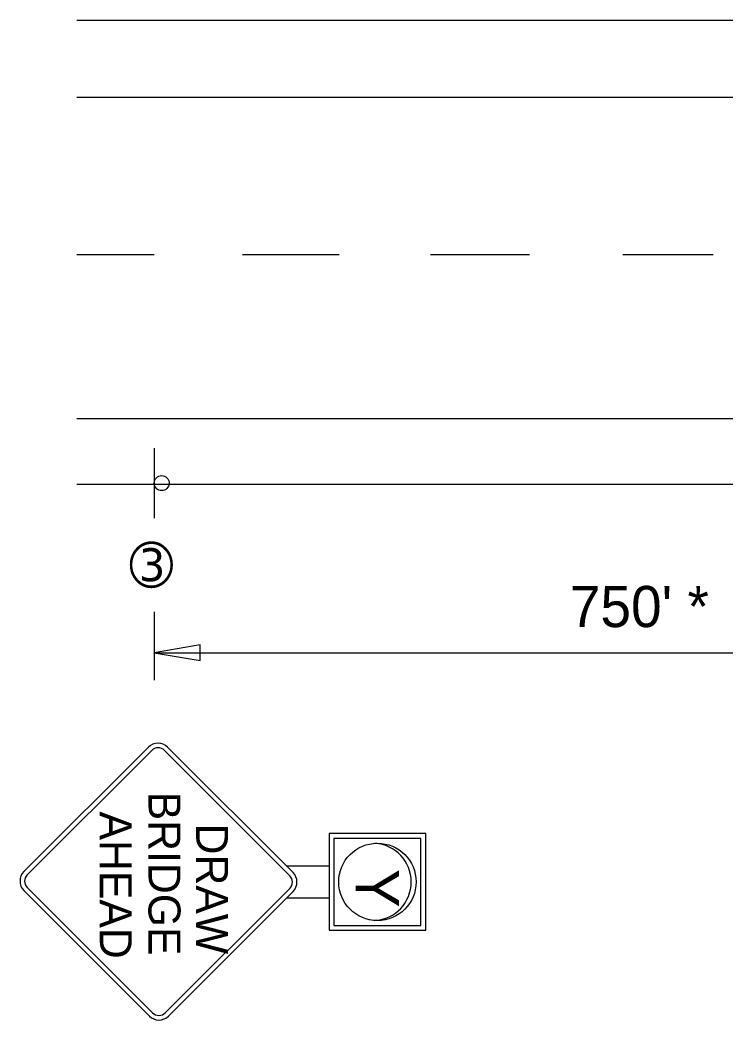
# Model space of a CAD drawing. Extents: x 15 to 764, y 7 to 487.
# Drawn here: x 17.2 to 77.2, y 347.6 to 432.6 of the extents above; entities that cross this region are included whole.
import ezdxf

# ---------------------------------------------------------------- set-up
doc = ezdxf.new("R2010")
doc.units = 0
for name, color, linetype in [('Default', 7, 'Continuous'), ('Dimension', 7, 'Continuous'), ('TextStructures', 7, 'Continuous')]:
    doc.layers.add(name, color=color, linetype=linetype)

msp = doc.modelspace()

# ---------------------------------------------------------------- linework, layer by layer
at = {"layer": 'Default'}
for p, q in [((22.063, 432.626), (366.864, 432.626)), ((22.063, 426.064), (366.864, 426.064)), ((22.063, 412.687), (28.635, 412.687)), ((36.151, 412.687), (44.369, 412.687)), ((52.111, 412.687), (60.533, 412.687)), ((68.478, 412.687), (76.153, 412.687)), ((22.063, 398.745), (366.864, 398.745)), ((28.637, 396.213), (28.637, 390.268)), ((22.063, 393.153), (366.864, 393.153)), ((28.646, 382.31), (28.646, 376.494)), ((28.646, 378.825), (114.544, 378.825)), ((17.568, 360.214), (28.153, 370.793)), ((29.778, 370.793), (40.438, 360.13)), ((17.843, 359.941), (28.428, 370.519)), ((29.505, 370.519), (40.163, 359.855)), ((43.501, 363.44), (43.501, 355.22)), ((51.721, 363.44), (43.501, 363.44)), ((51.721, 355.22), (51.721, 363.44)), ((43.912, 363.029), (43.912, 355.631)), ((51.31, 363.029), (43.912, 363.029)), ((51.31, 355.631), (51.31, 363.029)), ((39.861, 360.707), (43.49, 360.707)), ((17.568, 358.587), (28.227, 347.925)), ((17.843, 358.862), (28.501, 348.198)), ((29.578, 348.198), (40.162, 358.778)), ((29.852, 347.925), (40.437, 358.503)), ((39.923, 357.99), (43.49, 357.99)), ((43.912, 355.631), (51.31, 355.631)), ((43.501, 355.22), (51.721, 355.22))]:
    msp.add_line(p, q, dxfattribs=at)
for centre, radius in [((29.274, 393.241), 0.637), ((47.611, 359.33), 3.288)]:
    msp.add_circle(centre, radius, dxfattribs=at)
for centre, radius, start, end in [((28.966, 369.98), 1.15, 44.98473, 134.98571), ((28.966, 369.98), 0.762, 44.98473, 134.98571), ((47.2, 359.33), 3.288, 273.58332, 86.41668), ((18.381, 359.401), 1.15, 134.98573, 224.98455), ((18.381, 359.401), 0.762, 134.98573, 224.98455), ((39.624, 359.317), 0.762, 314.98524, 44.9843), ((39.624, 359.317), 1.15, 314.98524, 44.9843), ((29.039, 348.737), 1.15, 224.98483, 314.9852), ((29.039, 348.737), 0.762, 224.98483, 314.9852)]:
    msp.add_arc(centre, radius, start, end, dxfattribs=at)
at = {"layer": 'Dimension'}
msp.add_lwpolyline([(28.646, 378.825), (32.551, 378.163), (32.551, 379.486)], close=True, dxfattribs=at)

# ---------------------------------------------------------------- texts
at = {"layer": 'Default'}
for s, height, p in [('BRIDGE', 2.7176, (28.152, 367.005)), ('AHEAD', 2.7176, (24.014, 365.318)), ('DRAW', 2.7176, (32.2, 364.293)), ('Y', 3.699, (45.762, 360.44))]:
    msp.add_text(s, height=height, rotation=270, dxfattribs=at).set_placement(p)
at = {"layer": 'TextStructures'}
msp.add_text('➂', height=3.5, dxfattribs=at).set_placement((26.546, 384.556))
msp.add_text("750' *", height=3.5, rotation=0.00072, dxfattribs=at).set_placement((63.966, 380.999))

doc.saveas('drawing.dxf')
